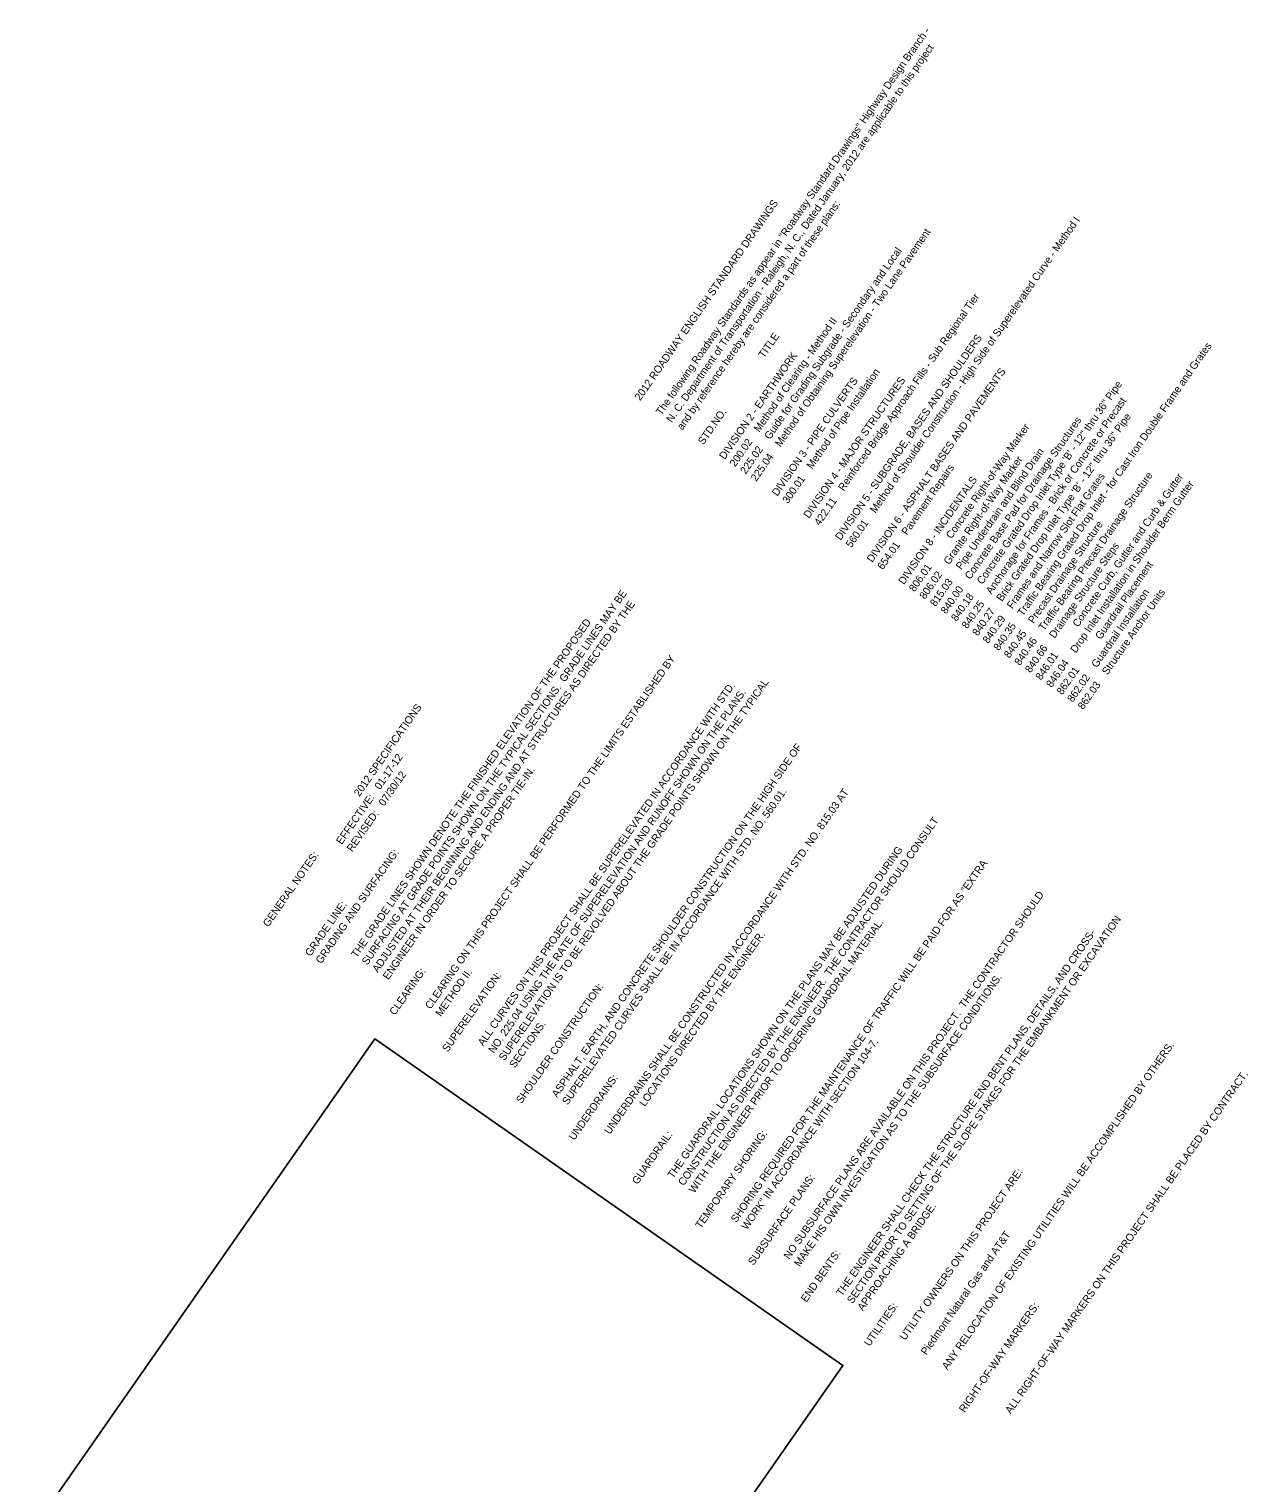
# Model space of a CAD drawing. Extents: x 1731327 to 1735374, y 884856 to 889832.
# Drawn here: x 1732640 to 1733526, y 886810 to 887867 of the extents above; entities that cross this region are included whole.
import ezdxf

# ---------------------------------------------------------------- set-up
doc = ezdxf.new("R2010")
doc.units = 0
doc.layers.add('Default', color=7, linetype='Continuous')
doc.layers.add('Exist Structure Minor Pipes RCP 24 Inch', color=7, linetype='Continuous')

msp = doc.modelspace()

# ---------------------------------------------------------------- linework, layer by layer
at = {"layer": 'Exist Structure Minor Pipes RCP 24 Inch'}
msp.add_lwpolyline([(1732980.3, 886535.2), (1733231.7, 886895.6), (1732891.5, 887133), (1732640.1, 886772.6)], close=True, dxfattribs=at)

# ---------------------------------------------------------------- texts
at = {"layer": 'Default'}
for s, p in [('The following Roadway Standards as appear in "Roadway Standard Drawings" Highway Design Branch -', (1733099.7, 887586.1)), ('N. C. Department of Transportation - Raleigh, N. C., Dated January, 2012 are applicable to this project', (1733107.3, 887580.8)), ('2012 ROADWAY ENGLISH STANDARD DRAWINGS', (1733084.3, 887596.8)), ('and by reference hereby are considered a part of these plans:', (1733115, 887575.4)), ('560.01    Method of Shoulder Construction - High Side of Superelevated Curve - Method I', (1733237.7, 887489.8)), ('225.04    Method of Obtaining Superelevation - Two Lane Pavement', (1733168.7, 887538)), ('225.02    Guide for Grading Subgrade - Secondary and Local', (1733161, 887543.3)), ('422.11    Reinforced Bridge Approach Fills - Sub Regional Tier', (1733214.7, 887505.9)), ('200.02    Method of Clearing - Method II', (1733153.3, 887548.7)), ('STD.NO.                       TITLE', (1733130.3, 887564.7)), ('DIVISION 5 - SUBGRADE, BASES AND SHOULDERS', (1733230, 887495.2)), ('840.35    Traffic Bearing Grated Drop Inlet - for Cast Iron Double Frame and Grates', (1733345, 887414.9)), ('DIVISION 2 - EARTHWORK', (1733145.7, 887554)), ('DIVISION 3 - PIPE CULVERTS', (1733184, 887527.3)), ('300.01    Method of Pipe Installation ', (1733191.7, 887521.9)), ('DIVISION 4 - MAJOR STRUCTURES', (1733207, 887511.2)), ('DIVISION 6 - ASPHALT BASES AND PAVEMENTS', (1733253, 887479.1)), ('840.18     Concrete Grated Drop Inlet Type \'B\' - 12" thru 36" Pipe', (1733314.3, 887436.3)), ('840.25    Anchorage for Frames - Brick or Concrete or Precast', (1733322, 887430.9)), ('840.00    Concrete Base Pad for Drainage Structures', (1733306.7, 887441.6)), ('840.27    Brick Grated Drop Inlet Type \'B\' - 12" thru 36" Pipe', (1733329.7, 887425.6)), ('806.01            Concrete Right-of-Way Marker', (1733283.7, 887457.7)), ('815.03     Pipe Underdrain and Blind Drain', (1733299, 887447)), ('806.02    Granite Right-of-Way Marker', (1733291.3, 887452.3)), ('654.01    Pavement Repairs', (1733260.7, 887473.8)), ('DIVISION 8 - INCIDENTALS', (1733276, 887463)), ('840.29    Frames and Narrow Slot Flat Grates', (1733337.3, 887420.2)), ('840.46    Traffic Bearing Precast Drainage Structure', (1733360.3, 887404.2)), ('846.01            Concrete Curb, Gutter and Curb & Gutter', (1733375.7, 887393.5)), ('846.04    Drop Inlet Installation in Shoulder Berm Gutter', (1733383.4, 887388.1)), ('840.45    Precast Drainage Structure', (1733352.7, 887409.5)), ('840.66    Drainage Structure Steps', (1733368, 887398.8)), ('862.01             Guardrail Placement', (1733391, 887382.8)), ('         SURFACING AT GRADE POINTS SHOWN ON THE TYPICAL SECTIONS.  GRADE LINES MAY BE ', (1732875.4, 887171.2)), ('862.02    Guardrail Installation', (1733398.7, 887377.4)), ('862.03    Structure Anchor Units', (1733406.4, 887372.1)), ('         ADJUSTED AT THEIR BEGINNING AND ENDING AND AT STRUCTURES AS DIRECTED BY THE ', (1732883, 887165.8)), ('         THE GRADE LINES SHOWN DENOTE THE FINISHED ELEVATION OF THE PROPOSED ', (1732867.7, 887176.5)), ('         CLEARING ON THIS PROJECT SHALL BE PERFORMED TO THE LIMITS ESTABLISHED BY ', (1732921.4, 887139.1)), ('         SUPERELEVATION IS TO BE REVOLVED ABOUT THE GRADE POINTS SHOWN ON THE TYPICAL ', (1732975, 887101.6)), ('         ALL CURVES ON THIS PROJECT SHALL BE SUPERELEVATED IN ACCORDANCE WITH STD. ', (1732959.7, 887112.3)), ('         NO. 225.04 USING THE RATE OF SUPERELEVATION AND RUNOFF SHOWN ON THE PLANS.', (1732967.4, 887107)), ('GENERAL NOTES:                         2012 SPECIFICATIONS', (1732814, 887214)), ('                                       EFFECTIVE:   01-17-12', (1732821.7, 887208.6)), ('         ASPHALT, EARTH, AND CONCRETE SHOULDER CONSTRUCTION ON THE HIGH SIDE OF', (1733013.4, 887074.9)), ('         ENGINEER IN ORDER TO SECURE A PROPER TIE-IN.  ', (1732890.7, 887160.5)), ('                                       REVISED:   07/30/12', (1732829.4, 887203.3)), ('         SUPERELEVATED CURVES SHALL BE IN ACCORDANCE WITH STD. NO. 560.01.', (1733021.1, 887069.5)), ('         UNDERDRAINS SHALL BE CONSTRUCTED IN ACCORDANCE WITH STD. NO. 815.03 AT ', (1733051.7, 887048.1)), ('         CONSTRUCTION AS DIRECTED BY THE ENGINEER.  THE CONTRACTOR SHOULD CONSULT', (1733105.4, 887010.7)), ('GRADING AND SURFACING:  ', (1732852.4, 887187.2)), ('         THE GUARDRAIL LOCATIONS SHOWN ON THE PLANS MAY BE ADJUSTED DURING ', (1733097.7, 887016)), ('         SHORING REQUIRED FOR THE MAINTENANCE OF TRAFFIC WILL BE PAID FOR AS "EXTRA ', (1733143.7, 886983.9)), ('         NO SUBSURFACE PLANS ARE AVAILABLE ON THIS PROJECT.  THE CONTRACTOR SHOULD ', (1733182.1, 886957.2)), ('GRADE LINE:  ', (1732844.7, 887192.6)), ('         SECTION PRIOR TO SETTING OF THE SLOPE STAKES FOR THE EMBANKMENT OR EXCAVATION ', (1733228.1, 886925)), ('         WITH THE ENGINEER PRIOR TO ORDERING GUARDRAIL MATERIAL.', (1733113.1, 887005.3)), ('LOCATIONS DIRECTED BY THE ENGINEER.  ', (1733087.7, 887083.4)), ('         THE ENGINEER SHALL CHECK THE STRUCTURE END BENT PLANS, DETAILS, AND CROSS-', (1733220.4, 886930.4)), ('CLEARING:  ', (1732906, 887149.8)), ('         METHOD II.', (1732929, 887133.7)), ('SUPERELEVATION:  ', (1732944.4, 887123)), ('SHOULDER CONSTRUCTION:  ', (1732998.1, 887085.6)), ('         MAKE HIS OWN INVESTIGATION AS TO THE SUBSURFACE CONDITIONS.  ', (1733189.7, 886951.8)), ('         SECTIONS.  ', (1732982.7, 887096.3)), ('         WORK" IN ACCORDANCE WITH SECTION 104-7.  ', (1733151.4, 886978.6)), ('         ANY RELOCATION OF EXISTING UTILITIES WILL BE ACCOMPLISHED BY OTHERS.  ', (1733297.1, 886876.9)), ('UNDERDRAINS:  ', (1733036.4, 887058.8)), ('         ALL RIGHT-OF-WAY MARKERS ON THIS PROJECT SHALL BE PLACED BY CONTRACT.  ', (1733343.1, 886844.8)), ('GUARDRAIL:  ', (1733082.4, 887026.7)), ('TEMPORARY SHORING:  ', (1733128.4, 886994.6)), ('SUBSURFACE PLANS:  ', (1733166.7, 886967.9)), ('         UTILITY OWNERS ON THIS PROJECT ARE:', (1733266.4, 886898.3)), ('         APPROACHING A BRIDGE.  ', (1733235.7, 886919.7)), ('         Piedmont Natural Gas and AT&T', (1733281.8, 886887.6)), ('END BENTS:  ', (1733205.1, 886941.1)), ('UTILITIES:  ', (1733251.1, 886909)), ('RIGHT-OF-WAY MARKERS:  ', (1733320.1, 886860.8))]:
    msp.add_text(s, height=5.5, rotation=55.0911, dxfattribs=at).set_placement(p)

doc.saveas('drawing.dxf')
